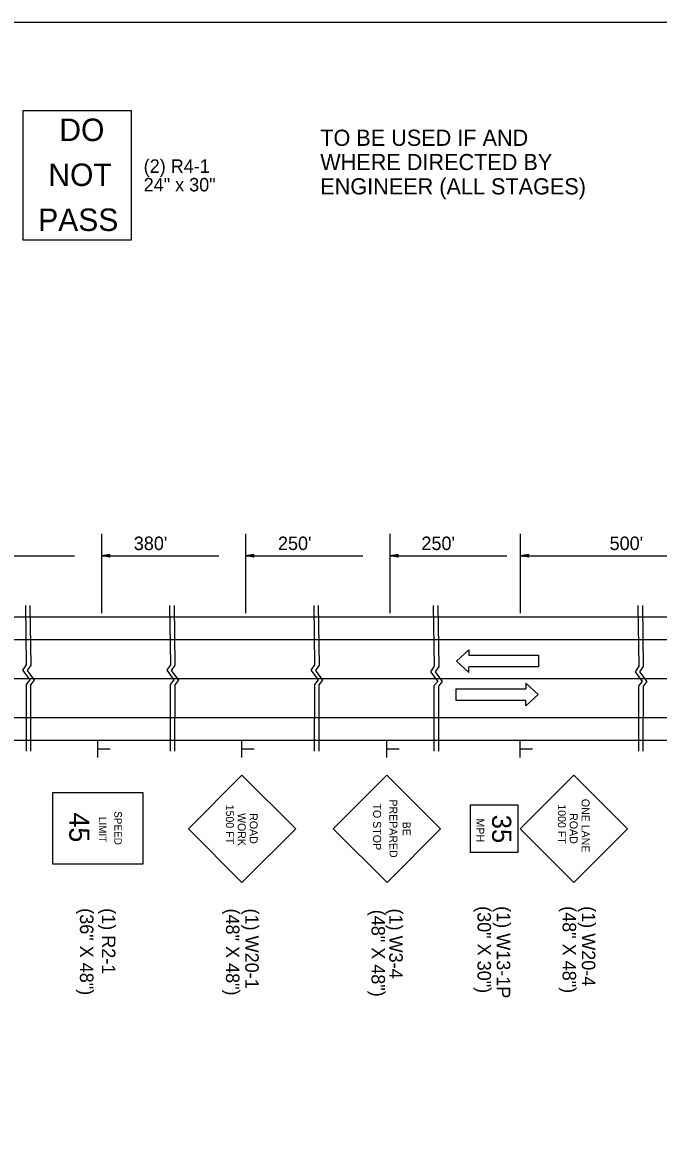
# Model space of a CAD drawing. Extents: x 1806907 to 1812607, y 675071 to 676228.
# Drawn here: x 1809345.6 to 1809628.7, y 675570.7 to 676070.3 of the extents above; entities that cross this region are included whole.
import ezdxf

# ---------------------------------------------------------------- set-up
doc = ezdxf.new("R2010")
doc.units = 0
for name, color, linetype in [('Default', 7, 'Continuous'), ('Dimensions', 7, 'Continuous'), ('DSN_DRFT_Named-Boundary', 7, 'Continuous'), ('R_MOT', 7, 'Continuous'), ('Stage 1', 7, 'Continuous')]:
    doc.layers.add(name, color=color, linetype=linetype)

msp = doc.modelspace()

# ---------------------------------------------------------------- linework, layer by layer
at = {"layer": 'Default'}
for p, q in [((1809380.75, 675842.78), (1809380.75, 675807.57)), ((1809444.91, 675842.78), (1809444.91, 675807.57)), ((1809509.07, 675842.78), (1809509.07, 675807.57)), ((1809567.17, 675842.78), (1809567.17, 675807.57)), ((1809316.59, 675832.99), (1809368.78, 675832.99)), ((1809384.5, 675833.55), (1809380.75, 675832.99)), ((1809380.75, 675832.99), (1809432.94, 675832.99)), ((1809384.5, 675832.42), (1809380.75, 675832.99)), ((1809384.5, 675833.45), (1809381.37, 675832.99)), ((1809384.5, 675832.52), (1809381.37, 675832.99)), ((1809384.5, 675833.36), (1809382.02, 675832.99)), ((1809384.5, 675832.61), (1809382.02, 675832.99)), ((1809384.5, 675833.27), (1809382.64, 675832.99)), ((1809384.5, 675832.71), (1809382.64, 675832.99)), ((1809384.5, 675833.17), (1809383.28, 675832.99)), ((1809384.5, 675832.8), (1809383.28, 675832.99)), ((1809384.5, 675833.07), (1809383.91, 675832.99)), ((1809384.5, 675832.9), (1809383.91, 675832.99)), ((1809384.5, 675832.42), (1809384.5, 675833.55)), ((1809448.66, 675833.55), (1809444.91, 675832.99)), ((1809444.91, 675832.99), (1809497.1, 675832.99)), ((1809448.66, 675832.42), (1809444.91, 675832.99)), ((1809448.66, 675833.45), (1809445.54, 675832.99)), ((1809448.66, 675832.52), (1809445.54, 675832.99)), ((1809448.66, 675833.36), (1809446.18, 675832.99)), ((1809448.66, 675832.61), (1809446.18, 675832.99)), ((1809448.66, 675833.27), (1809446.8, 675832.99)), ((1809448.66, 675832.71), (1809446.8, 675832.99)), ((1809448.66, 675833.17), (1809447.44, 675832.99)), ((1809448.66, 675832.8), (1809447.44, 675832.99)), ((1809448.66, 675833.07), (1809448.07, 675832.99)), ((1809448.66, 675832.9), (1809448.07, 675832.99)), ((1809448.66, 675832.42), (1809448.66, 675833.55)), ((1809512.82, 675833.55), (1809509.07, 675832.99)), ((1809509.07, 675832.99), (1809561.26, 675832.99)), ((1809512.82, 675832.42), (1809509.07, 675832.99)), ((1809512.82, 675833.45), (1809509.7, 675832.99)), ((1809512.82, 675832.52), (1809509.7, 675832.99)), ((1809512.82, 675833.36), (1809510.34, 675832.99)), ((1809512.82, 675832.61), (1809510.34, 675832.99)), ((1809512.82, 675833.27), (1809510.97, 675832.99)), ((1809512.82, 675832.71), (1809510.97, 675832.99)), ((1809512.82, 675833.17), (1809511.6, 675832.99)), ((1809512.82, 675832.8), (1809511.6, 675832.99)), ((1809512.82, 675833.07), (1809512.23, 675832.99)), ((1809512.82, 675832.9), (1809512.23, 675832.99)), ((1809512.82, 675832.42), (1809512.82, 675833.55)), ((1809570.92, 675833.55), (1809567.17, 675832.99)), ((1809567.17, 675832.99), (1809657.91, 675832.99)), ((1809570.92, 675832.42), (1809567.17, 675832.99)), ((1809570.92, 675833.45), (1809567.8, 675832.99)), ((1809570.92, 675832.52), (1809567.8, 675832.99)), ((1809570.92, 675833.36), (1809568.44, 675832.99)), ((1809570.92, 675832.61), (1809568.44, 675832.99)), ((1809570.92, 675833.27), (1809569.07, 675832.99)), ((1809570.92, 675832.71), (1809569.07, 675832.99)), ((1809570.92, 675833.17), (1809569.7, 675832.99)), ((1809570.92, 675832.8), (1809569.7, 675832.99)), ((1809570.92, 675833.07), (1809570.33, 675832.99)), ((1809570.92, 675832.9), (1809570.33, 675832.99)), ((1809570.92, 675832.42), (1809570.92, 675833.55)), ((1809227.51, 675805.87), (1810285.86, 675805.87)), ((1809227.51, 675795.87), (1809776.27, 675795.87)), ((1809227.51, 675778.48), (1809663.82, 675778.48)), ((1809227.51, 675761.1), (1809776.27, 675761.1)), ((1809227.51, 675751.1), (1810285.86, 675751.1)), ((1809379.16, 675743.28), (1809379.16, 675751.1)), ((1809443.32, 675743.28), (1809443.32, 675751.1)), ((1809507.81, 675743.28), (1809507.81, 675751.1)), ((1809567.17, 675743.28), (1809567.17, 675751.1)), ((1809379.28, 675747.17), (1809384.62, 675747.17)), ((1809443.44, 675747.17), (1809448.78, 675747.17)), ((1809507.92, 675747.17), (1809513.26, 675747.17)), ((1809567.29, 675747.17), (1809572.63, 675747.17)), ((1809419.44, 675711.63), (1809443.32, 675735.54)), ((1809467.23, 675711.63), (1809443.32, 675735.54)), ((1809483.95, 675711.59), (1809507.81, 675735.54)), ((1809531.73, 675711.67), (1809507.81, 675735.54)), ((1809567.17, 675711.63), (1809591.06, 675735.54)), ((1809614.96, 675711.63), (1809591.06, 675735.54)), ((1809443.32, 675687.73), (1809419.44, 675711.63)), ((1809443.32, 675687.73), (1809467.23, 675711.63)), ((1809507.89, 675687.73), (1809483.95, 675711.59)), ((1809507.89, 675687.73), (1809531.73, 675711.67)), ((1809591.06, 675687.73), (1809567.17, 675711.63)), ((1809591.06, 675687.73), (1809614.96, 675711.63))]:
    msp.add_line(p, q, dxfattribs=at)
for points in [[(1809346.92, 675810.87), (1809347.32, 675784.54), (1809345.7, 675782.13), (1809348.86, 675777.8), (1809347.2, 675775.8), (1809347.19, 675746.1)], [(1809348.92, 675810.87), (1809349.32, 675784.46), (1809347.7, 675782.04), (1809350.86, 675777.71), (1809349.2, 675775.71), (1809349.19, 675746.1)], [(1809411.08, 675810.87), (1809411.49, 675784.54), (1809409.86, 675782.13), (1809413.03, 675777.8), (1809411.36, 675775.8), (1809411.35, 675746.1)], [(1809413.08, 675810.87), (1809413.48, 675784.46), (1809411.86, 675782.04), (1809415.02, 675777.71), (1809413.36, 675775.71), (1809413.35, 675746.1)], [(1809475.24, 675810.87), (1809475.65, 675784.54), (1809474.02, 675782.13), (1809477.19, 675777.8), (1809475.52, 675775.8), (1809475.51, 675746.1)], [(1809477.24, 675810.87), (1809477.64, 675784.46), (1809476.02, 675782.04), (1809479.18, 675777.71), (1809477.52, 675775.71), (1809477.51, 675746.1)], [(1809528.46, 675810.87), (1809528.87, 675783.91), (1809527.25, 675781.49), (1809530.41, 675777.17), (1809528.74, 675775.17), (1809528.74, 675746.1)], [(1809530.46, 675810.87), (1809530.87, 675783.83), (1809529.24, 675781.41), (1809532.41, 675777.08), (1809530.74, 675775.08), (1809530.74, 675746.1)], [(1809619.51, 675810.87), (1809619.92, 675783.91), (1809618.29, 675781.49), (1809621.46, 675777.17), (1809619.79, 675775.17), (1809619.78, 675746.1)], [(1809621.5, 675810.87), (1809621.91, 675783.83), (1809620.29, 675781.41), (1809623.45, 675777.08), (1809621.79, 675775.08), (1809621.78, 675746.1)]]:
    msp.add_lwpolyline(points, dxfattribs=at)
for points in [[(1809399.25, 675695.9), (1809359.08, 675695.9), (1809359.08, 675727.77), (1809399.25, 675727.77)], [(1809566.1, 675722.2), (1809566.1, 675701.07), (1809544.98, 675701.07), (1809544.98, 675722.2)]]:
    msp.add_lwpolyline(points, close=True, dxfattribs=at)
at = {"layer": 'DSN_DRFT_Named-Boundary'}
msp.add_lwpolyline([(1808931.68, 675071.2), (1810581.68, 675071.2), (1810581.68, 676070.26), (1808931.68, 676070.26)], close=True, dxfattribs=at)
at = {"layer": 'R_MOT'}
for p, q in [((1809538.73, 675786.19), (1809544.22, 675791.19)), ((1809544.22, 675791.19), (1809544.22, 675788.69)), ((1809575.44, 675788.69), (1809544.22, 675788.69)), ((1809575.44, 675783.69), (1809575.44, 675788.69)), ((1809544.22, 675781.19), (1809538.73, 675786.19)), ((1809575.44, 675783.69), (1809544.22, 675783.69)), ((1809544.22, 675781.19), (1809544.22, 675783.69)), ((1809538.48, 675773.86), (1809569.7, 675773.86)), ((1809538.48, 675773.86), (1809538.48, 675768.86)), ((1809569.7, 675776.36), (1809575.18, 675771.36)), ((1809569.7, 675776.36), (1809569.7, 675773.86)), ((1809538.48, 675768.86), (1809569.7, 675768.86)), ((1809575.18, 675771.36), (1809569.7, 675766.36)), ((1809569.7, 675766.36), (1809569.7, 675768.86))]:
    msp.add_line(p, q, dxfattribs=at)
at = {"layer": 'Stage 1'}
msp.add_lwpolyline([(1809346, 676031.14), (1809394.02, 676031.14), (1809394.02, 675973.5), (1809346, 675973.5)], close=True, dxfattribs=at)

# ---------------------------------------------------------------- texts
at = {"layer": 'Default'}
for s, height, rotation, p in [('DO', 10, 360, (1809362.02, 676017.51)), ('NOT', 10, 360, (1809357.13, 675997.51)), ('PASS', 10, 360, (1809352.61, 675977.51)), ('TO STOP', 3.544, 270.0006, (1809501.68, 675722.89)), ('PREPARED', 3.521, 270.1003, (1809508.93, 675724.67)), ('ONE LANE', 3.521, 270.0004, (1809594.46, 675724.93)), ('45', 8.897, 270, (1809366.48, 675718.86)), ('SPEED', 3.32, 270, (1809386.51, 675719.48)), ('1500 FT', 3.522, 270.0006, (1809436.16, 675722.35)), ('WORK', 3.52, 270, (1809441.45, 675718.61)), ('ROAD', 3.521, 270.0004, (1809446.73, 675718.54)), ('35', 8.51, 270, (1809554.64, 675717.86)), ('1000 FT', 3.522, 270.0006, (1809583.9, 675722.49)), ('ROAD', 3.52, 270, (1809589.18, 675718.54)), ('LIMIT', 3.32, 270, (1809379.65, 675716.93)), ('BE', 3.521, 270.1004, (1809514.82, 675714.79)), ('MPH', 3.522, 270.0006, (1809547.58, 675716.18)), ('(36" X 48")', 6, 270, (1809371.2, 675676.3)), ('(1) R2-1', 6, 270, (1809380.98, 675676.3)), ('(48" X 48")', 6, 270, (1809436.19, 675676.14)), ('(1) W20-1', 6, 270, (1809444.75, 675676.14)), ('(48" X 48")', 6, 270, (1809500.96, 675675.61)), ('(1) W3-4', 6, 270, (1809508.86, 675676.14)), ('(30" X 30")', 6, 270, (1809548.14, 675677.21)), ('(1) W13-1P', 6, 270, (1809556.71, 675677.21)), ('(48" X 48")', 6, 270, (1809586.01, 675677.21)), ('(1) W20-4', 6, 270, (1809594.57, 675677.21))]:
    msp.add_text(s, height=height, rotation=rotation, dxfattribs=at).set_placement(p)
for s, p in [("380'", (1809395.16, 675835.59)), ("250'", (1809459.32, 675835.59)), ("250'", (1809523.17, 675835.59)), ("500'", (1809606.93, 675835.59))]:
    msp.add_text(s, height=6, dxfattribs=at).set_placement(p)
at = {"layer": 'Dimensions'}
for s, p in [('TO BE USED IF AND', (1809478.16, 676015.37)), ('WHERE DIRECTED BY', (1809478.16, 676004.57)), ('ENGINEER (ALL STAGES)', (1809478.16, 675993.77))]:
    msp.add_text(s, height=7.2, dxfattribs=at).set_placement(p)
at = {"layer": 'Stage 1'}
for s, p in [('(2) R4-1', (1809399.56, 676003.36)), ('24" x 30"', (1809399.56, 675995.11))]:
    msp.add_text(s, height=6, dxfattribs=at).set_placement(p)

doc.saveas('drawing.dxf')
